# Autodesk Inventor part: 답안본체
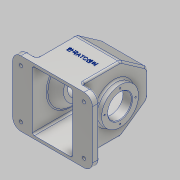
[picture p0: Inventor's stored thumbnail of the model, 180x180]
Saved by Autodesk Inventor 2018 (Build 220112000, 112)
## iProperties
Created: 2022-12
Part Number: 답안본체
Material: 알루미늄 6061
Document SubType Name: Modeling
Designer: home
Density: 2.7 g/cm^3
Appearance: 알루미늄 - 평지
Author: home
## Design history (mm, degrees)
sketch "스케치1"
  geometry: L1 (0, 0)-(65, 0); L2 (0, 0)-(0, 110); L3 (0, 110)-(65, 110); L4 (65, 0)-(110, 31.509); L5 (65, 110)-(110, 78.491); L6 (110, 31.509)-(110, 78.491)
  constraints: 12 end point, 2 vertical, 1 horizontal, 1 perpendicular
  dimensions: "d7" = 65 distance of L1.start L1.end; "d8" = 110 distance of L1.start L2.end; "d9" = 65 distance of L2.end L3.end; "d10" = 35 deg angle of L4 L1; "d11" = 35 deg angle of L5 L3; "d12" = 110 distance between parallel lines of L2 L6
extrude "돌출1" new body sketch "스케치1" stored distance "d13" = 77; taper "d14" = 0 deg
sketch "스케치2"
  geometry: L1 (-28.5, 110)-(105.5, 110); L2 (105.5, 110)-(105.5, 0); L3 (105.5, 0)-(-28.5, 0); L4 (-28.5, 0)-(-28.5, 110); L5 (0, 110)-(77, 110) reference; L6 (0, 0)-(0, 110) reference; 5 further points
  constraints: 8 end point, 4 midpoint, 2 parallel, 1 coincident, 1 horizontal, 1 horizontal alignment, 1 perpendicular
  dimensions: "d15" = 134 distance of L2.end L3.end; "d16" = 110 distance of L1.end L2.end
extrude "돌출2" join sketch "스케치2" distance "d17" = 12; taper "d18" = 0 deg
feature "쉘1" dims "d19" = 5
sketch "스케치3"
  geometry: L1 (-23.5, 5)-(-23.5, 105) reference; L2 (-23.5, 105)-(100.5, 105) reference; L3 (100.5, 105)-(100.5, 5) reference; L4 (100.5, 5)-(-23.5, 5) reference; L5 (105.5, 110)-(-28.5, 110) reference; L6 (-28.5, 110)-(-28.5, 0) reference; L7 (-28.5, 0)-(105.5, 0) reference; L8 (105.5, 0)-(105.5, 110) reference; L9 (5, 5)-(5, 105) reference; L10 (-23.5, 105)-(5, 105) reference; L11 (-23.5, 5)-(-23.5, 105) reference; L12 (5, 5)-(-23.5, 5) reference; L13 (72, 105)-(72, 5) reference; L14 (100.5, 5)-(72, 5) reference; L15 (100.5, 105)-(100.5, 5) reference; L16 (72, 105)-(100.5, 105) reference; L17 (105.5, 110)-(-28.5, 110) reference; L18 (105.5, 110)-(105.5, 0); L19 (-28.5, 0)-(-28.5, 110); L20 (5, 110)-(5, 0); L21 (72, 110)-(72, 0); L22 (-28.5, 110)-(5, 110); L23 (72, 110)-(105.5, 110); L24 (105.5, 0)-(72, 0); L25 (5, 0)-(-28.5, 0); 1 further point
  constraints: 16 end point, 5 parallel, 3 point on line, 2 horizontal, 2 perpendicular
extrude "돌출3" join sketch "스케치3" distance "d20" = 12; taper "d21" = 0 deg
sketch "스케치4"
  geometry: L1 (105, -12)-(5, -12) reference; L2 (55, -12)-(55, 53); C1 r 37.5 at (55, 53); 1 further point
  constraints: 2 end point, 1 centre point, 1 coincident, 1 midpoint, 1 vertical
  dimensions: "d22" = 65 distance of L2.start L2.end; "d23" = 75 diameter of C1
extrude "돌출4" join sketch "스케치4" distance "d24" = 5; taper "d25" = 0 deg
sketch "스케치5"
  geometry: L1 (-105, -12)-(-5, -12) reference; L2 (-55, -12)-(-55, 53); C1 r 31 at (-55, 53); 1 further point
  constraints: 2 end point, 1 centre point, 1 coincident, 1 midpoint, 1 vertical
  dimensions: "d26" = 65 distance of L2.start L2.end; "d27" = 62 diameter of C1
extrude "돌출5" join sketch "스케치5" distance "d28" = 10; taper "d29" = 0 deg
node "작업 평면1"
sketch "스케치6"
  geometry: L1 (77, -65)-(105.5, -65) reference; L2 (105.5, -65)-(105.5, -77) reference; L3 (105.5, -77)-(72, -77) reference; L4 (72, -77)-(72, 40) reference; L5 (72, 40)-(5, 40) reference; L6 (5, 40)-(5, -77) reference; L7 (5, -77)-(-28.5, -77) reference; L8 (-28.5, -77)-(-28.5, -65) reference; L9 (-28.5, -65)-(0, -65) reference; L10 (0, -65)-(0, -49.5) reference; L11 (0, -49.5)-(-5, -49.5) reference; L12 (-5, -49.5)-(-5, 25.5) reference; L13 (-5, 25.5)-(0, 25.5) reference; L14 (0, 25.5)-(0, 45) reference; L15 (0, 45)-(77, 45) reference; L16 (77, 45)-(77, 19) reference; L17 (77, 19)-(87, 19) reference; L18 (87, 19)-(87, -43) reference; L19 (87, -43)-(77, -43) reference; L20 (77, -43)-(77, -65) reference; L21 (-5, 25.5)-(-5, -49.5) reference; L22 (5, -1.576)-(5, -77) reference; L23 (5, -12)-(19, -12); L24 (72, -77)-(5, -77) reference; L25 (19, -12)-(19, -39); L26 (19, -39)-(5, -53); L27 (5, -53)-(5, -12); 1 further point
  constraints: 8 end point, 2 point on line, 1 collinear, 1 vertical
  dimensions: "d32" = 65 distance between parallel lines of L23 L24; "d35" = 135 deg angle of L22 L26; "d36" = 54 diameter of L25.end L23; "d100" = 24 distance between parallel lines of L25 L12
revolve "회전1" sketch "스케치6" stored, may be unused: angle "d38" = 90 deg
hole "구멍1" diameter "d41" = 40; stored, may be unused: countersink angle "d45" = 90 deg, drill point angle "d47" = 118 deg; dims "d39" = 10, "d40" = 10, "d42" = 6, "d43" = 4, "d44" = 2, "d46" = 8
sketch "스케치7"
  geometry: L1 (0, 0)-(77, 0) reference; L2 (77, 46.981)-(77, 0) reference; L3 (0, 46.981)-(77, 46.981) reference; L4 (0, 0)-(0, 46.981) reference; C1 r 6 at (38.5, 23.491); 1 further point
  constraints: 1 centre point
  dimensions: "d48" = 12 diameter of C1
extrude "돌출6" join sketch "스케치7" distance "d49" = 4; taper "d50" = 0 deg
hole "구멍2" diameter "d53" = 5.188; stored, may be unused: countersink angle "d57" = 90 deg, drill point angle "d59" = 118 deg; dims "d51" = 10, "d52" = 10, "d54" = 12, "d55" = 4, "d56" = 2, "d58" = 16
fillet "모깎기1" dims "d60" = 14
sketch "스케치8"
  geometry: A1 r 14 centre (-14.5, -14) between (-14.5, 0) and (-28.5, -14) reference; A2 r 14 centre (-14.5, -96) between (-28.5, -96) and (-14.5, -110) reference; A3 r 14 centre (91.5, -96) between (91.5, -110) and (105.5, -96) reference; A4 r 14 centre (91.5, -14) between (105.5, -14) and (91.5, 0) reference; 5 further points
  constraints: 4 coincident
hole "구멍3" sketch "스케치8" at (-14.5, -14), (-14.5, -96), (91.5, -96), (91.5, -14) diameter "d61" = 5.5; stored, may be unused: countersink angle "d65" = 90 deg, drill point angle "d67" = 118 deg; dims "d62" = 12, "d63" = 15, "d64" = 2, "d66" = 16
sketch "스케치9" dims "d68" = 58
  geometry: C1 r 31 at (0, 0) reference; 3 further points
  constraints: 1 coincident, 1 vertical alignment, 2 other
hole "구멍4" sketch "스케치9" at (0, 29) diameter "d69" = 2.459; stored, may be unused: countersink angle "d73" = 90 deg, drill point angle "d75" = 118 deg; dims "d70" = 6, "d71" = 15, "d72" = 2, "d74" = 8
sketch "스케치10" dims "d79" = 52
  geometry: C1 r 20 at (0, 0) reference; C2 r 31 at (0, 0) reference; 3 further points
  constraints: 1 coincident, 1 vertical alignment, 2 other
hole "구멍5" sketch "스케치10" at (0, 26) diameter "d80" = 2.459; stored, may be unused: countersink angle "d84" = 90 deg, drill point angle "d86" = 118 deg; dims "d81" = 6, "d82" = 15, "d83" = 2, "d85" = 8
fillet "모깎기2" dims "d90" = 10
fillet "모깎기3" dims "d91" = 3
sketch "스케치11"
  geometry: L1 (106, 0)-(0, 0) reference; L2 (14.5, 73.847)-(14.5, 15) reference; 2 further points
  constraints: 1 other
  dimensions: "d92" = 50 distance from line of point (53, 50) L1; "d93" = 38.5 distance from line of point (53, 50) L2
feature "엠보싱1" sketch "스케치11" dims "d94" = 0.5, "d95" = 0
chamfer "모따기1" distance "d96" = 1; stored, may be unused: second distance "d97" = 2, angle "d98" = 45 deg
fillet "모깎기4" dims "d99" = 3
node "솔리드1"
pattern_circular "원형 패턴1" dims angle "d77" = 360 deg
pattern_circular "원형 패턴2" dims angle "d88" = 360 deg
node "투영된 루프1"
node "투영된 루프2"
node "투영된 루프3"
node "투영된 루프4"
node "투영된 루프5"
node "절단 모서리 투영1"
